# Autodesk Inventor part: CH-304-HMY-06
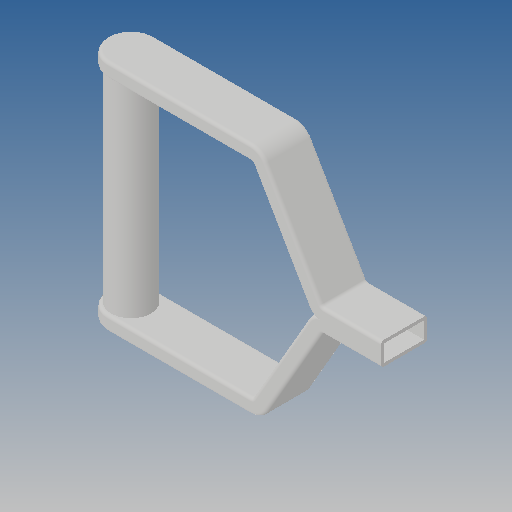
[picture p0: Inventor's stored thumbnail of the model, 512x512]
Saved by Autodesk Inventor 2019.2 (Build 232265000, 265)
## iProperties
Created: 2015-08
Part Number: CH-304-HMY-06
Material: Ogólny
Document SubType Name: Modeling
Designer: CADENGINEERING4
Density: 1 g/cm^3
Appearance: Domyślna
Author: CADENGINEERING4
Revision Number: ÈÎºÎ
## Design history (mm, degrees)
feature "NONE"
node "Bryła1"
